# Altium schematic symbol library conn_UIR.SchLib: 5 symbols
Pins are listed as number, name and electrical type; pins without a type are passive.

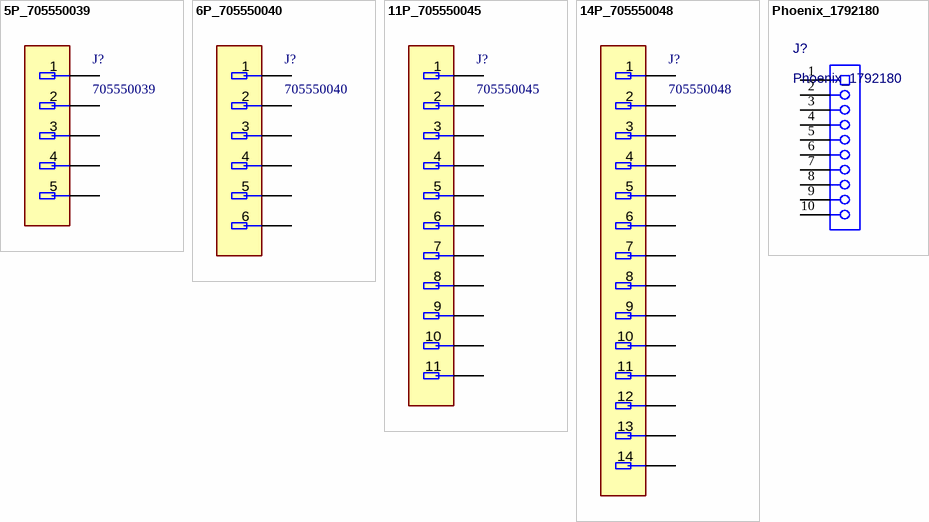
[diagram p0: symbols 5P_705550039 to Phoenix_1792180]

## 5P_705550039
designator J?, comment 705550039
Connector Header Through Hole, Right Angle 5 position 0.100" (2.54mm)
footprint 705550039
pins: 1, 2, 3, 4, 5

## 6P_705550040
designator J?, comment 705550040
Connector Header Through Hole, Right Angle 6 position 0.100" (2.54mm)
footprint 705550040 (Footprint not found)
pins: 1, 2, 3, 4, 5, 6

## 11P_705550045
designator J?, comment 705550045
Connector Header Through Hole, Right Angle 11 position 0.100" (2.54mm)
footprint 705550045 (Footprint not found)
pins: 1, 2, 3, 4, 5, 6, 7, 8, 9, 10, 11

## 14P_705550048
designator J?, comment 705550048
Connector Header Through Hole, Right Angle 14 position 0.100" (2.54mm)
footprint 705550048
pins: 1, 2, 3, 4, 5, 6, 7, 8, 9, 10, 11, 12, 13, 14

## Phoenix_1792180
designator J?
Phoenix_1792180, 1x10p, 7.5mm pitch
footprint Phoenix_1792180 (Receptacle, 7.5mm, 10x1, TH)
pins: 1, 2, 3, 4, 5, 6, 7, 8, 9, 10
